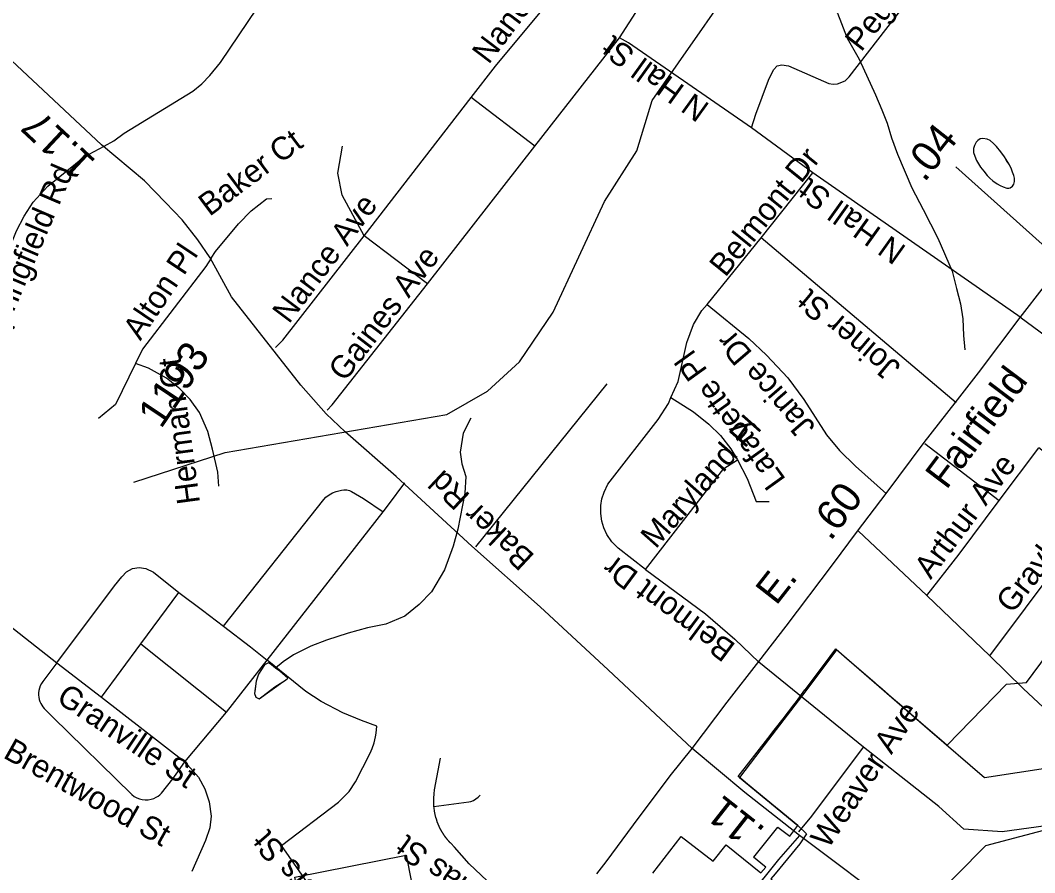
# Model space of a CAD drawing. Extents: x 1715610 to 1720914, y 798298 to 802505.
# Drawn here: x 1715962.9 to 1716054.7, y 799408.2 to 799485.2 of the extents above; entities that cross this region are included whole.
import ezdxf

# ---------------------------------------------------------------- set-up
doc = ezdxf.new("R2010")
doc.units = 0
doc.layers.add('Default', color=7, linetype='Continuous')

msp = doc.modelspace()

# ---------------------------------------------------------------- linework, layer by layer
at = {"layer": 'Default'}
for p, q in [((1716017.148, 799483.626), (1716022.782, 799492.412)), ((1716009.489, 799473.825), (1716017.148, 799483.626)), ((1715994.035, 799465.739), (1716003.717, 799478.247)), ((1716009.489, 799473.825), (1716003.717, 799478.247)), ((1716034.622, 799471.42), (1716029.068, 799475.491)), ((1715999.766, 799461.38), (1716009.489, 799473.825)), ((1716029.945, 799465.554), (1716034.622, 799471.42)), ((1716053.454, 799458.309), (1716034.622, 799471.42)), ((1715999.766, 799461.38), (1715994.035, 799465.739)), ((1716025.078, 799459.524), (1716029.945, 799465.554)), ((1716047.571, 799450.629), (1716029.945, 799465.554)), ((1716053.454, 799458.309), (1716060.198, 799453.382)), ((1716004.159, 799437.627), (1716016.031, 799452.336)), ((1716044.758, 799446.97), (1716051.489, 799441.797)), ((1716051.489, 799441.797), (1716055.076, 799446.561)), ((1715985.277, 799427.357), (1715995.754, 799440.792)), ((1716038.736, 799439.05), (1716044.922, 799433.205)), ((1715973.85, 799428.848), (1715977.292, 799433.47)), ((1716044.922, 799433.205), (1716050.637, 799427.744)), ((1715970.303, 799424.012), (1715973.85, 799428.848)), ((1715973.85, 799428.848), (1715981.608, 799422.655)), ((1715981.608, 799422.655), (1715985.277, 799427.357)), ((1715966.264, 799427.141), (1715970.303, 799424.012)), ((1716039.216, 799419.489), (1716029.747, 799427.19)), ((1715970.303, 799424.012), (1715977.838, 799418.164)), ((1715977.838, 799418.164), (1715981.608, 799422.655))]:
    msp.add_line(p, q, dxfattribs=at)
for points in [[(1716023.718, 799419.386), (1716016.126, 799426.487), (1716009.969, 799432.19), (1716003.784, 799437.668), (1715996.928, 799443.961), (1715992.338, 799448.007), (1715990.609, 799449.635), (1715988.316, 799452.217), (1715982.034, 799460.209), (1715980.122, 799463.74), (1715978.992, 799465.379), (1715977.581, 799467.165), (1715976.083, 799468.756), (1715974.189, 799470.715), (1715970.305, 799473.958), (1715962.149, 799481.58), (1715959.118, 799485.028), (1715957.834, 799487.223), (1715956.743, 799489.456), (1715954.262, 799498.464), (1715953.463, 799502.756), (1715953.361, 799508.585), (1715955.096, 799517.509), (1715956.471, 799526.044)], [(1715970.531, 799473.851), (1715971.392, 799474.306), (1715972.328, 799475.028), (1715978.545, 799478.806), (1715979.374, 799479.488), (1715980.095, 799480.219), (1715981.046, 799481.392), (1715985.985, 799488.741), (1715992.438, 799498.555), (1715993.248, 799499.705), (1715994.866, 799501.432), (1715995.93, 799502.264), (1715997.346, 799503.2), (1716001.869, 799505.742), (1716007.831, 799509.269)], [(1716032.089, 799496.777), (1716032.217, 799496.425), (1716033.317, 799493.406), (1716034.523, 799490.159), (1716035.8, 799487.708), (1716036.866, 799485.873), (1716037.733, 799483.594), (1716038.809, 799481.699), (1716040.292, 799478.471), (1716040.857, 799477.137), (1716041.339, 799475.913), (1716041.747, 799474.583), (1716042.273, 799473.115), (1716043.565, 799470.071), (1716044.592, 799468.104), (1716045.927, 799465.506), (1716047.211, 799462.524), (1716047.628, 799460.973), (1716047.984, 799459.57), (1716048.174, 799458.228), (1716048.242, 799456.706), (1716048.36, 799455.415)], [(1716029.068, 799475.491), (1716029.472, 799476.739), (1716030.627, 799479.799), (1716031.072, 799480.752), (1716031.41, 799481.115), (1716031.828, 799481.185), (1716032.42, 799481.092), (1716036.059, 799479.501), (1716036.466, 799479.441), (1716036.848, 799479.467), (1716037.549, 799479.754), (1716037.92, 799480.094), (1716046.624, 799491.365), (1716046.96, 799491.877), (1716047.425, 799492.151), (1716047.692, 799492.211), (1716048.104, 799492.19), (1716048.731, 799491.895), (1716050.022, 799490.989), (1716050.278, 799490.942), (1716050.664, 799491.089), (1716054.213, 799495.528)], [(1715973.217, 799443.45), (1715981.463, 799446.15), (1716001.534, 799449.57), (1716005.187, 799451.681), (1716008.081, 799454.325), (1716011.136, 799458.822), (1716015.78, 799468.827), (1716018.718, 799473.403), (1716020.078, 799477.964), (1716029.838, 799491.924)], [(1716003.717, 799478.247), (1716005.91, 799481.078), (1716012.965, 799489.567)], [(1716029.068, 799475.491), (1716017.953, 799483.176), (1716017.148, 799483.626)], [(1716023.718, 799419.386), (1716026.887, 799423.569), (1716029.743, 799427.256), (1716032.221, 799430.438), (1716036.411, 799435.995), (1716038.667, 799439.029), (1716041.249, 799442.428), (1716044.687, 799447.045), (1716047.501, 799450.637), (1716049.591, 799453.332), (1716053.374, 799458.342), (1716057.772, 799464.026), (1716060.127, 799467.055), (1716062.421, 799470.146), (1716064.648, 799473.194), (1716065.567, 799474.645)], [(1716052.575, 799471.769), (1716052.411, 799472.144), (1716052.15, 799472.533), (1716051.96, 799472.872), (1716051.629, 799473.312), (1716051.223, 799473.798), (1716050.948, 799474.091), (1716050.65, 799474.35), (1716050.374, 799474.484), (1716049.987, 799474.536), (1716049.748, 799474.493), (1716049.552, 799474.361), (1716049.394, 799474.206), (1716049.234, 799473.895), (1716049.157, 799473.63), (1716049.167, 799473.255), (1716049.259, 799472.928), (1716049.424, 799472.552), (1716049.695, 799472.102), (1716049.791, 799471.931), (1716050.075, 799471.58), (1716050.397, 799471.2), (1716050.635, 799470.933), (1716050.898, 799470.701), (1716051.294, 799470.431), (1716051.569, 799470.295), (1716051.846, 799470.158), (1716052.182, 799470.035), (1716052.338, 799470.032), (1716052.459, 799470.056), (1716052.679, 799470.223), (1716052.803, 799470.403), (1716052.853, 799470.63), (1716052.856, 799470.944), (1716052.809, 799471.185), (1716052.694, 799471.477), (1716052.575, 799471.769)], [(1716052.575, 799471.769), (1716052.411, 799472.144), (1716051.96, 799472.872), (1716051.629, 799473.312), (1716051.223, 799473.798), (1716050.948, 799474.091), (1716050.65, 799474.35), (1716050.374, 799474.484), (1716049.987, 799474.536), (1716049.748, 799474.493), (1716049.552, 799474.361), (1716049.394, 799474.206), (1716049.234, 799473.895), (1716049.157, 799473.63), (1716049.167, 799473.255), (1716049.259, 799472.928), (1716049.424, 799472.552), (1716049.791, 799471.931), (1716050.075, 799471.58), (1716050.397, 799471.2), (1716050.635, 799470.933), (1716050.898, 799470.701), (1716051.294, 799470.431), (1716051.569, 799470.295), (1716051.846, 799470.158), (1716052.182, 799470.035), (1716052.338, 799470.032), (1716052.459, 799470.056), (1716052.679, 799470.223), (1716052.803, 799470.403), (1716052.853, 799470.63), (1716052.856, 799470.944), (1716052.809, 799471.185), (1716052.694, 799471.477), (1716052.575, 799471.769)], [(1715954.479, 799445.642), (1715955.299, 799448.004), (1715959.91, 799459.535), (1715962.603, 799466.183), (1715963.312, 799467.501), (1715964.117, 799468.785), (1715965.444, 799470.223), (1715968.726, 799472.878), (1715970.531, 799473.851)], [(1715994.035, 799465.739), (1715992.061, 799469.41), (1715991.675, 799471.399), (1715992.077, 799473.829)], [(1716066.982, 799472.26), (1716058.839, 799461.866), (1716047.549, 799471.964)], [(1715980.211, 799463.725), (1715980.586, 799464.305), (1715982.667, 799466.808), (1715983.822, 799468.001), (1715985.204, 799469.079), (1715985.706, 799469.103)], [(1715986.03, 799455.626), (1715986.684, 799456.288), (1715994.035, 799465.739)], [(1715980.211, 799463.725), (1715979.719, 799462.955), (1715973.996, 799455.486), (1715973.359, 799454.175)], [(1715990.714, 799449.963), (1715991.164, 799450.44), (1715999.766, 799461.38)], [(1716021.787, 799451.107), (1716022.448, 799452.575), (1716023.234, 799456.089), (1716023.825, 799457.712), (1716024.589, 799458.978), (1716025.078, 799459.524)], [(1716025.078, 799459.524), (1716028.835, 799456.46), (1716030.436, 799454.956), (1716032.347, 799452.895), (1716033.822, 799450.939), (1716035.858, 799447.754), (1716037.036, 799446.322), (1716038.476, 799444.91), (1716041.285, 799442.418)], [(1715973.359, 799454.175), (1715971.562, 799450.493), (1715970.007, 799449.228)], [(1715980.89, 799443.092), (1715980.816, 799444.368), (1715980.317, 799446.446), (1715979.899, 799448.047), (1715979.15, 799449.749), (1715978.3, 799450.943), (1715977.39, 799451.905), (1715976.174, 799452.87), (1715974.534, 799453.752), (1715973.359, 799454.175)], [(1716019.492, 799435.566), (1716017.009, 799437.489), (1716016.44, 799438.076), (1716015.995, 799438.738), (1716015.725, 799439.317), (1716015.543, 799439.92), (1716015.44, 799440.627), (1716015.449, 799441.337), (1716015.552, 799441.962), (1716015.738, 799442.57), (1716016.091, 799443.283), (1716020.641, 799449.126), (1716021.56, 799450.572), (1716021.787, 799451.107)], [(1716021.787, 799451.107), (1716023.816, 799449.817), (1716025.219, 799448.709), (1716026.274, 799447.678), (1716027.218, 799446.474), (1716027.8, 799445.476)], [(1716003.685, 799449.257), (1716003.006, 799447.877), (1716002.733, 799446.167), (1716002.866, 799445.126), (1716003.24, 799443.977), (1716003.15, 799442.456), (1716002.51, 799439.206), (1716002.106, 799437.689), (1716001.323, 799435.538), (1716000.129, 799433.557), (1715999.029, 799432.412), (1715997.727, 799431.354), (1715996.016, 799430.624), (1715994.36, 799430.281), (1715992.604, 799429.795), (1715990.654, 799429.176), (1715989.224, 799428.625), (1715987.646, 799427.859), (1715986.734, 799427.22), (1715986.028, 799426.646)], [(1716050.637, 799427.744), (1716060.227, 799440.562), (1716060.399, 799441.068), (1716060.444, 799441.463), (1716060.375, 799441.987), (1716060.15, 799442.471), (1716059.907, 799442.778), (1716055.076, 799446.561)], [(1716019.492, 799435.566), (1716026.564, 799444.694), (1716027.8, 799445.476)], [(1716027.8, 799445.476), (1716028.683, 799443.806), (1716029.51, 799441.727), (1716030.681, 799441.719)], [(1715995.754, 799440.792), (1715996.242, 799441.401), (1715997.728, 799443.403)], [(1715981.334, 799430.435), (1715990.41, 799441.899), (1715990.594, 799442.103), (1715990.869, 799442.328), (1715991.177, 799442.501), (1715991.509, 799442.619), (1715991.519, 799442.622), (1715992, 799442.745), (1715992.199, 799442.779), (1715992.466, 799442.77), (1715992.725, 799442.705), (1715992.895, 799442.624), (1715993.977, 799441.998), (1715995.754, 799440.792)], [(1716044.922, 799433.205), (1716047.848, 799436.961), (1716051.489, 799441.797)], [(1715966.264, 799427.141), (1715971.474, 799434.074), (1715972.136, 799434.91), (1715972.561, 799435.358), (1715973.109, 799435.645), (1715973.706, 799435.747), (1715974.299, 799435.667), (1715974.979, 799435.32), (1715977.292, 799433.47)], [(1716019.492, 799435.566), (1716024.926, 799431.565), (1716027.556, 799429.275), (1716029.747, 799427.19)], [(1715977.292, 799433.47), (1715979.436, 799431.891), (1715981.334, 799430.435)], [(1715960.791, 799431.641), (1715960.978, 799431.241), (1715966.264, 799427.141)], [(1715981.334, 799430.435), (1715983.754, 799428.56), (1715985.277, 799427.357)], [(1716027.992, 799416.768), (1716027.884, 799416.856), (1716030.547, 799420.292), (1716031.132, 799421.046), (1716031.932, 799422.077), (1716032.903, 799423.331), (1716033.131, 799423.624), (1716033.905, 799424.673), (1716033.922, 799424.697), (1716035.188, 799426.382), (1716036.176, 799427.697), (1716036.698, 799428.394), (1716037.523, 799427.681), (1716038.544, 799426.799), (1716039.173, 799426.253), (1716040.062, 799425.485), (1716040.19, 799425.373), (1716040.349, 799425.237), (1716040.887, 799424.772), (1716041.711, 799424.057), (1716042.667, 799423.231), (1716043.486, 799422.523), (1716044.388, 799421.742), (1716046.283, 799420.104), (1716046.781, 799419.672), (1716052.14, 799425.207), (1716053.936, 799425.362), (1716055.851, 799427.915)], [(1716027.992, 799416.768), (1716027.884, 799416.856), (1716030.547, 799420.292), (1716031.132, 799421.046), (1716031.932, 799422.077), (1716032.903, 799423.331), (1716033.131, 799423.624), (1716033.905, 799424.673), (1716033.922, 799424.697), (1716035.188, 799426.382), (1716036.176, 799427.697), (1716036.698, 799428.394), (1716037.523, 799427.681), (1716038.544, 799426.799), (1716039.173, 799426.253), (1716040.062, 799425.485), (1716040.19, 799425.373), (1716040.349, 799425.237), (1716040.887, 799424.772), (1716041.711, 799424.057), (1716042.667, 799423.231), (1716043.486, 799422.523), (1716044.388, 799421.742), (1716046.283, 799420.104), (1716046.781, 799419.672), (1716052.14, 799425.207), (1716053.936, 799425.362), (1716055.851, 799427.915)], [(1716066.09, 799418.121), (1716066.043, 799419.13), (1716061.964, 799418.527), (1716050.151, 799416.727), (1716045.184, 799421.023), (1716036.774, 799428.297), (1716033.996, 799424.599), (1716029.915, 799419.282), (1716027.992, 799416.768)], [(1716066.09, 799418.121), (1716066.043, 799419.13), (1716061.964, 799418.527), (1716050.151, 799416.727), (1716045.184, 799421.023), (1716036.774, 799428.297), (1716033.996, 799424.599), (1716029.915, 799419.282), (1716027.992, 799416.768)], [(1716000.207, 799396.439), (1715991.906, 799403.278), (1715990.939, 799404.348), (1715986.562, 799410.62), (1715991.724, 799414.543), (1715992.687, 799415.501), (1715993.266, 799416.376), (1715994.58, 799418.955), (1715994.777, 799419.389), (1715994.953, 799419.906), (1715995.074, 799420.443), (1715995.121, 799420.762), (1715995.189, 799421.4), (1715993.796, 799421.921), (1715992.13, 799422.614), (1715990.161, 799423.644), (1715988.781, 799424.547), (1715985.277, 799427.357)], [(1716050.637, 799427.744), (1716053.64, 799424.802), (1716056.376, 799422.247), (1716057.701, 799422.462)], [(1715966.264, 799427.141), (1715964.978, 799425.447), (1715964.861, 799425.263), (1715964.758, 799425.057), (1715964.675, 799424.838), (1715964.627, 799424.615), (1715964.606, 799424.41), (1715964.603, 799424.199), (1715964.622, 799424.013), (1715964.66, 799423.824), (1715964.723, 799423.638), (1715964.794, 799423.459), (1715964.886, 799423.296), (1715964.999, 799423.139), (1715965.114, 799422.99), (1715965.899, 799422.226), (1715973.041, 799415.211), (1715973.254, 799415.049), (1715973.478, 799414.919), (1715973.723, 799414.826), (1715973.982, 799414.761), (1715974.252, 799414.734), (1715974.522, 799414.737), (1715974.79, 799414.787), (1715975.035, 799414.868), (1715975.228, 799414.971), (1715975.404, 799415.069), (1715975.563, 799415.195), (1715975.715, 799415.339), (1715976.75, 799416.648), (1715977.058, 799417.057), (1715977.838, 799418.164)], [(1715986.028, 799426.646), (1715985.657, 799426.953), (1715985.406, 799427.124), (1715985.029, 799426.96), (1715984.499, 799426.107), (1715984.277, 799425.472), (1715984.196, 799424.737), (1715984.142, 799424.35), (1715984.235, 799424.024), (1715984.548, 799423.864), (1715984.902, 799424.15), (1715985.972, 799424.944), (1715986.7, 799425.396), (1715986.921, 799425.562), (1715987.139, 799425.728), (1715986.423, 799426.379), (1715986.028, 799426.646)], [(1715986.028, 799426.646), (1715985.657, 799426.953), (1715985.406, 799427.124), (1715985.029, 799426.96), (1715984.499, 799426.107), (1715984.277, 799425.472), (1715984.142, 799424.35), (1715984.235, 799424.024), (1715984.548, 799423.864), (1715986.7, 799425.396), (1715986.921, 799425.562), (1715987.139, 799425.728), (1715986.423, 799426.379), (1715986.028, 799426.646)], [(1716015.078, 799408.037), (1716015.925, 799409.149), (1716018.413, 799412.474), (1716021.713, 799416.908), (1716023.718, 799419.386)], [(1716033.43, 799411.513), (1716028.474, 799415.409), (1716023.718, 799419.386)], [(1716033.358, 799411.854), (1716034.545, 799413.258), (1716039.216, 799419.489)], [(1716062.924, 799413.392), (1716051.753, 799411.85), (1716048.28, 799412.094), (1716046.023, 799414.128), (1716039.216, 799419.489)], [(1715977.838, 799418.164), (1715979.068, 799416.778), (1715979.624, 799415.739), (1715980.039, 799414.561), (1715980.218, 799413.273), (1715980.074, 799412.202), (1715979.708, 799411.073), (1715978.448, 799408.255)], [(1716000.357, 799414.143), (1716000.343, 799414.303), (1716000.335, 799414.6), (1716000.334, 799414.895), (1716000.363, 799415.268), (1716000.417, 799415.644), (1716000.935, 799418.496)], [(1716027.992, 799416.768), (1716033.278, 799412.418), (1716034.063, 799411.658), (1716033.44, 799410.772), (1716031.215, 799408.064), (1716030.827, 799407.591), (1716032.622, 799405.99), (1716034.505, 799404.505), (1716028.086, 799396.637), (1716026.7, 799394.938), (1716030.527, 799391.781), (1716033.853, 799396.082), (1716033.881, 799396.05), (1716040.929, 799405.076), (1716051.74, 799396.682)], [(1716027.992, 799416.768), (1716033.278, 799412.418), (1716034.063, 799411.658), (1716033.44, 799410.772), (1716031.215, 799408.064), (1716030.827, 799407.591), (1716032.622, 799405.99), (1716034.505, 799404.505), (1716028.086, 799396.637), (1716026.7, 799394.938), (1716030.527, 799391.781), (1716033.853, 799396.082), (1716033.881, 799396.05), (1716040.929, 799405.076), (1716051.74, 799396.682)], [(1716033.278, 799412.418), (1716031.384, 799413.961), (1716031.243, 799414.075), (1716029.569, 799415.477), (1716028.727, 799416.164), (1716028.105, 799416.675), (1716027.992, 799416.768)], [(1716033.278, 799412.418), (1716031.384, 799413.961), (1716031.243, 799414.075), (1716029.569, 799415.477), (1716028.727, 799416.164), (1716028.105, 799416.675), (1716027.992, 799416.768)], [(1716065.188, 799416.774), (1716063.706, 799416.544), (1716056.957, 799412.37), (1716050.226, 799410.593), (1716029.641, 799389.746)], [(1716000.357, 799414.143), (1716003.522, 799414.56), (1716003.696, 799414.604), (1716003.938, 799414.687), (1716004.158, 799414.821), (1716004.37, 799414.977), (1716004.545, 799415.161)], [(1716000.977, 799412.04), (1716000.966, 799412.054), (1716000.96, 799412.064), (1716000.957, 799412.079), (1716000.953, 799412.095), (1716000.94, 799412.104), (1716000.94, 799412.12), (1716000.927, 799412.129), (1716000.922, 799412.142), (1716000.912, 799412.159), (1716000.906, 799412.169), (1716000.903, 799412.184), (1716000.888, 799412.194), (1716000.894, 799412.21), (1716000.874, 799412.236), (1716000.872, 799412.248), (1716000.862, 799412.267), (1716000.852, 799412.274), (1716000.854, 799412.286), (1716000.843, 799412.3), (1716000.84, 799412.315), (1716000.833, 799412.336), (1716000.822, 799412.347), (1716000.822, 799412.363), (1716000.81, 799412.38), (1716000.799, 799412.401), (1716000.793, 799412.418), (1716000.794, 799412.431), (1716000.778, 799412.448), (1716000.774, 799412.463), (1716000.762, 799412.479), (1716000.768, 799412.488), (1716000.759, 799412.494), (1716000.765, 799412.503), (1716000.752, 799412.518), (1716000.742, 799412.537), (1716000.736, 799412.551), (1716000.735, 799412.565), (1716000.723, 799412.589), (1716000.713, 799412.606), (1716000.705, 799412.624), (1716000.706, 799412.64), (1716000.697, 799412.659), (1716000.688, 799412.665), (1716000.688, 799412.685), (1716000.673, 799412.701), (1716000.671, 799412.719), (1716000.655, 799412.73), (1716000.66, 799412.746), (1716000.66, 799412.756), (1716000.65, 799412.776), (1716000.643, 799412.793), (1716000.634, 799412.816), (1716000.632, 799412.827), (1716000.629, 799412.842), (1716000.62, 799412.848), (1716000.626, 799412.857), (1716000.61, 799412.868), (1716000.608, 799412.889), (1716000.576, 799412.989), (1716000.539, 799413.138), (1716000.464, 799413.427), (1716000.407, 799413.711), (1716000.367, 799414.012), (1716000.357, 799414.143)], [(1716005.159, 799407.428), (1716003.537, 799408.946), (1716002.208, 799410.46), (1716001.875, 799410.811), (1716001.859, 799410.824), (1716001.852, 799410.843), (1716001.834, 799410.855), (1716001.834, 799410.867), (1716001.801, 799410.877), (1716001.802, 799410.889), (1716001.786, 799410.903), (1716001.772, 799410.919), (1716001.759, 799410.934), (1716001.745, 799410.95), (1716001.728, 799410.961), (1716001.715, 799410.983), (1716001.701, 799410.999), (1716001.689, 799411.014), (1716001.675, 799411.03), (1716001.669, 799411.04), (1716001.66, 799411.046), (1716001.645, 799411.063), (1716001.633, 799411.077), (1716001.622, 799411.085), (1716001.616, 799411.096), (1716001.605, 799411.109), (1716001.595, 799411.116), (1716001.589, 799411.127), (1716001.584, 799411.139), (1716001.574, 799411.146), (1716001.564, 799411.16), (1716001.558, 799411.17), (1716001.546, 799411.178), (1716001.54, 799411.188), (1716001.528, 799411.204), (1716001.514, 799411.219), (1716001.508, 799411.23), (1716001.498, 799411.237), (1716001.488, 799411.253), (1716001.485, 799411.265), (1716001.465, 799411.281), (1716001.456, 799411.287), (1716001.443, 799411.309), (1716001.421, 799411.337), (1716001.416, 799411.347), (1716001.404, 799411.368), (1716001.387, 799411.38), (1716001.384, 799411.395), (1716001.374, 799411.401), (1716001.36, 799411.41), (1716001.359, 799411.428), (1716001.352, 799411.439), (1716001.346, 799411.45), (1716001.34, 799411.46), (1716001.328, 799411.468), (1716001.321, 799411.486), (1716001.312, 799411.492), (1716001.309, 799411.51), (1716001.3, 799411.516), (1716001.291, 799411.522), (1716001.279, 799411.537), (1716001.276, 799411.549), (1716001.252, 799411.574), (1716001.252, 799411.588), (1716001.234, 799411.6), (1716001.225, 799411.619), (1716001.219, 799411.629), (1716001.212, 799411.641), (1716001.206, 799411.651), (1716001.204, 799411.669), (1716001.188, 799411.679), (1716001.185, 799411.694), (1716001.176, 799411.7), (1716001.169, 799411.712), (1716001.155, 799411.731), (1716001.138, 799411.752), (1716001.131, 799411.774), (1716001.119, 799411.781), (1716001.116, 799411.796), (1716001.105, 799411.814), (1716001.093, 799411.832), (1716001.09, 799411.847), (1716001.079, 799411.854), (1716001.076, 799411.869), (1716001.063, 799411.878), (1716001.06, 799411.893), (1716001.048, 799411.914), (1716001.032, 799411.928), (1716001.029, 799411.943), (1716001.02, 799411.949), (1716001.014, 799411.969), (1716001.015, 799411.982), (1716001.004, 799411.996), (1716000.996, 799412.008), (1716000.99, 799412.018), (1716000.984, 799412.029), (1716000.977, 799412.04)], [(1716020.16, 799408.102), (1716022.724, 799411.414), (1716025.603, 799409.18), (1716026.771, 799410.672), (1716029.919, 799408.143), (1716030.358, 799408.66), (1716030.266, 799408.735), (1716029.254, 799409.544), (1716029.274, 799409.569), (1716030.001, 799410.467), (1716031.461, 799412.273), (1716032.54, 799411.453), (1716033.278, 799412.418)], [(1716020.16, 799408.102), (1716022.724, 799411.414), (1716025.603, 799409.18), (1716026.771, 799410.672), (1716029.919, 799408.143), (1716030.358, 799408.66), (1716030.266, 799408.735), (1716029.254, 799409.544), (1716029.274, 799409.569), (1716030.001, 799410.467), (1716031.461, 799412.273), (1716032.54, 799411.453), (1716033.278, 799412.418)], [(1716033.43, 799411.513), (1716031.525, 799409.344), (1716030.189, 799407.673), (1716025.976, 799402.654), (1716023.897, 799400.141), (1716021.022, 799396.438), (1716018.858, 799393.433), (1716017.998, 799392.239), (1716017.501, 799392.024), (1716016.787, 799391.986), (1716015.996, 799392.601), (1716015.442, 799393.058)], [(1716052.143, 799397.284), (1716051.134, 799398.065), (1716046.124, 799401.907), (1716039.369, 799407.046), (1716036.561, 799409.173), (1716033.43, 799411.513)]]:
    msp.add_lwpolyline(points, dxfattribs=at)
msp.add_lwpolyline([(1715989.776, 799397.695), (1715987.786, 799407.742), (1715997.833, 799409.733), (1715999.824, 799399.685)], close=True, dxfattribs=at)

# ---------------------------------------------------------------- texts
for s, height, rotation, p in [('Pegram Ave', 2.0663, 52.03542, (1716038.996, 799482.289)), ('Nance Ave', 2.0663, 52.90841, (1716005.303, 799481.166)), ('N Hall St', 2.0663, 144.27451, (1716025.387, 799477.576)), ('1.17', 2.7188, 136.93805, (1715969.881, 799472.494)), ('Baker Ct', 2.0663, 36.7544, (1715980.061, 799467.433)), ('.04', 2.7188, 51.69476, (1716044.717, 799470.499)), ('Belmont Dr', 2.0663, 51.07517, (1716026.706, 799461.919)), ('E Springfield Rd', 2.06625, 66.8835, (1715959.984, 799453.262)), ('N Hall St', 2.0663, 144.46995, (1716043.17, 799464.7)), ('Nance Ave', 2.0663, 53.11362, (1715987.244, 799457.705)), ('Alton Pl', 2.0663, 56.20506, (1715973.807, 799456.185)), ('Gaines Ave', 2.0663, 52.65271, (1715992.297, 799452.454)), ('Joiner St', 2.0663, 139.93461, (1716042.687, 799454.02)), ('Janice Dr', 2.0663, 130.68724, (1716034.94, 799448.511)), ('1193', 2.7188, 56.20506, (1715975.679, 799448.212)), ('Herman Ct', 2.0663, 97.64501, (1715979.206, 799441.604)), ('Lafayette Pl', 2.06625, 125.69652, (1716032.237, 799443.711)), ('Fairfield', 2.61, 53.04849, (1716046.7, 799442.708)), ('Maryland Pl', 2.06625, 48.56279, (1716020.417, 799437.365)), ('Arthur Ave', 2.0663, 53.10389, (1716045.28, 799434.599)), ('Baker Rd', 2.0663, 136.86596, (1716009.554, 799436.817)), ('.60', 2.7188, 52.77826, (1716036.226, 799438.063)), ('Graylyn Dr', 2.0663, 52.51961, (1716052.673, 799431.486)), ('Belmont Dr', 2.0663, 143.56032, (1716027.75, 799428.754)), ('E.', 2.61, 51.96489, (1716031.315, 799432.239)), ('Granville St', 2.06625, 326.2209, (1715966.104, 799423.661)), ('Weaver Ave', 2.0663, 56.20506, (1716036.004, 799410.223)), ('Brentwood St', 2.06625, 330.67743, (1715961.303, 799418.6)), ('.11', 2.7188, 141.82402, (1716030.446, 799412.129)), ('Chambers St', 2.06625, 130.70328, (1715995.864, 799399.953)), ('Thomas St', 2.0663, 144.03532, (1716008.728, 799403.815))]:
    msp.add_text(s, height=height, rotation=rotation, dxfattribs=at).set_placement(p)

doc.saveas('drawing.dxf')
